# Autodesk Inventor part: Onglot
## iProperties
Created: 2011-05
Part Number: Onglot
Document SubType Name: Modeling
Designer: 904Chiaki
Density: 1 g/cm^3
Mass: 56.6911 g
Surface Area: 159.147 cm^2
Volume: 56.6911 cm^3
Author: 904Chiaki
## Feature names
1. Extrusion1
2. Chamfer1
